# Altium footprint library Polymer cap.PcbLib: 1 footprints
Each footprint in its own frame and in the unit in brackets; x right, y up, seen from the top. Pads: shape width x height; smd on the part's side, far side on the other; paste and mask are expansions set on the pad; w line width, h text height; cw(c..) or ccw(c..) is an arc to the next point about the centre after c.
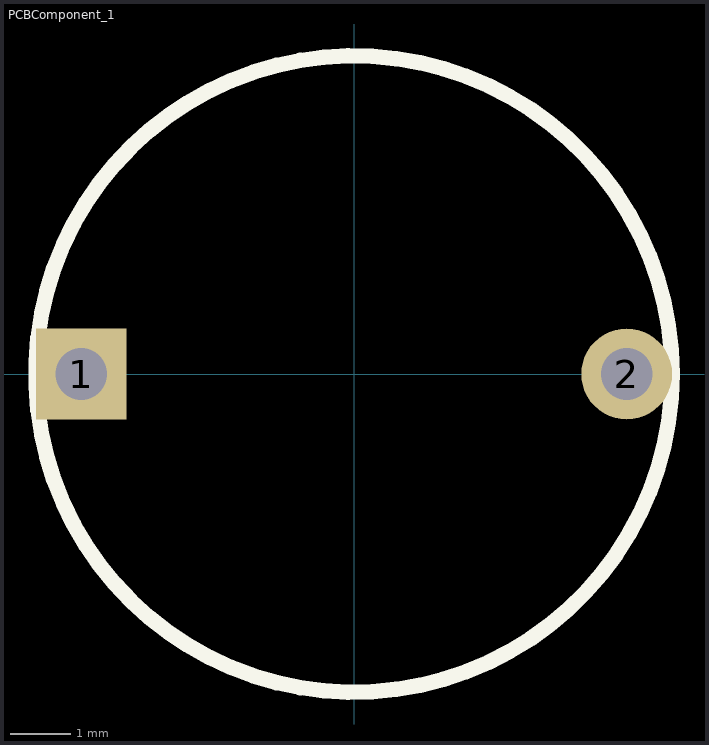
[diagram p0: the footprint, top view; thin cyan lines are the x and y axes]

## PCBComponent_1 [mm]
pads (2):
  rect 1.5x1.5 hole 0.85: 1(-4.5,0)
  round 1.5 hole 0.85: 2(4.5,0)
Top Overlay:
  circle w0.254: c0,0 r5.25
M5 Assembly Top:
  text ".Designator" at -2,-0.7 h1.85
